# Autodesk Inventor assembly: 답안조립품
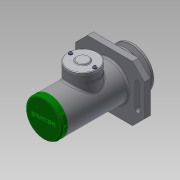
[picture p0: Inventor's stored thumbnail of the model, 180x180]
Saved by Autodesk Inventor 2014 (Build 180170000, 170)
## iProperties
Created: 2017-10
Part Number: 답안조립품
Document SubType Name: Assembly
Designer: NET
Author: NET
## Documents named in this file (20)
- C:\Users\NET\Desktop\471007V1031\답안조립품.iam
- C:\Users\NET\Desktop\471007V1031\본체.ipt
- C:\Users\NET\Desktop\471007V1031\부품\V-벨트풀리.ipt
- C:\Users\NET\Desktop\471007V1031\부품\너트 M10.ipt
- C:\Users\NET\Desktop\471007V1031\부품\멈춤링 15 x 1.ipt
- C:\Users\NET\Desktop\471007V1031\부품\멈춤링 35x1.6.ipt
- C:\Users\NET\Desktop\471007V1031\부품\베어링 15 x 35 x 11.ipt
- C:\Users\NET\Desktop\471007V1031\부품\볼트 M4 x 10.ipt
- C:\Users\NET\Desktop\471007V1031\부품\부시1.ipt
- C:\Users\NET\Desktop\471007V1031\부품\부시2.ipt
- C:\Users\NET\Desktop\471007V1031\부품\사이드 커버.ipt
- 사이드 커버.ipt
- C:\Users\NET\Desktop\471007V1031\부품\십자볼트 M3 x 10.ipt
- C:\Users\NET\Desktop\471007V1031\부품\오일 실 15 25 7.ipt
- C:\Users\NET\Desktop\471007V1031\부품\와셔 3x6.ipt
- C:\Users\NET\Desktop\471007V1031\부품\와셔 4x16.ipt
- C:\Users\NET\Desktop\471007V1031\부품\와셔 10x21.ipt
- C:\Users\NET\Desktop\471007V1031\부품\축.ipt
- C:\Users\NET\Desktop\471007V1031\부품\키 4 x 4 x 18.ipt
- C:\Users\NET\Desktop\471007V1031\부품\탑 커버.ipt
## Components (2 placed, 2 different names)
1. V-벨트풀리:1
2. ISO 4017 M4 x 10:1
